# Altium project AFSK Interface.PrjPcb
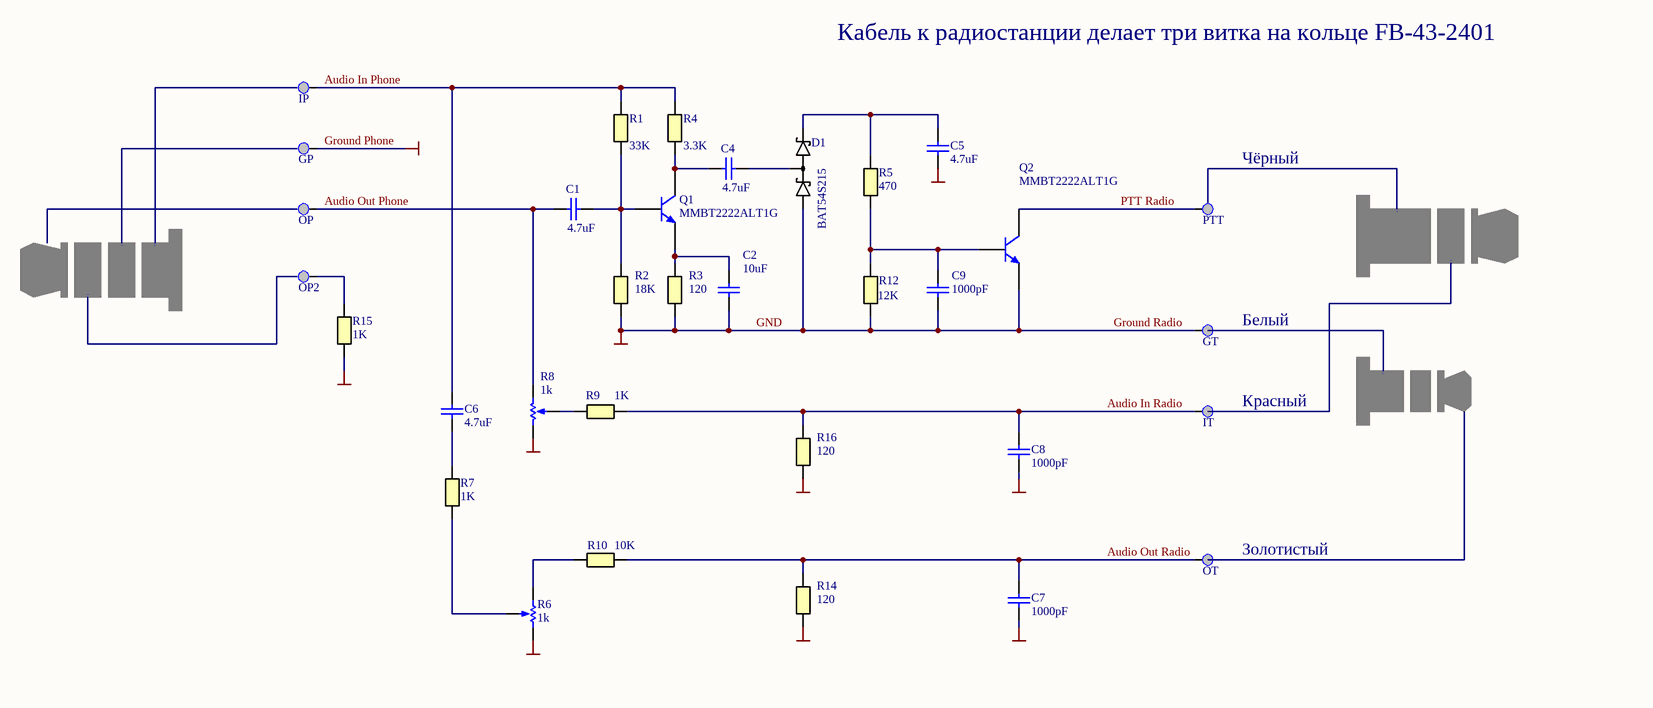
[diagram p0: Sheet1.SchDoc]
1 sheet, 33 parts. Net scope: global (net labels, ports and power ports of the same name join across sheets).
Board file: INTERFACE.PcbDoc

## Sheet Sheet1.SchDoc
size A3

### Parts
C1  value 4.7uF  [C0805]  (hidden comment: X7R-4.7UF-16V-20%-0805)
C2  value 10uF  [C0805]  (hidden comment: X5R-10UF-16V-20%-0805)
C4  value 4.7uF  [C0805]  (hidden comment: X7R-4.7UF-16V-20%-0805)
C5  value 4.7uF  [C0805]  (hidden comment: X7R-4.7UF-16V-20%-0805)
C6  value 4.7uF  [C0805]  (hidden comment: X7R-4.7UF-16V-20%-0805)
C7  value 1000pF  [C0805]  (hidden comment: NP0-1000PF-50V-5%-0805)
C8  value 1000pF  [C0805]  (hidden comment: NP0-1000PF-50V-5%-0805)
C9  value 1000pF  [C0805]  (hidden comment: NP0-1000PF-50V-5%-0805)
D1  BAT54S215  [SOT-23]
GP  PIN  [PIN]  (value not drawn)
GT  PIN  [PIN]  (value not drawn)
IP  PIN  [PIN]  (value not drawn)
IT  PIN  [PIN]  (value not drawn)
OP  PIN  [PIN]  (value not drawn)
OP2  PIN  [PIN]  (value not drawn)
OT  PIN  [PIN]  (value not drawn)
PTT  PIN  [PIN]  (value not drawn)
Q1  MMBT2222ALT1G  [SOT-23]
Q2  MMBT2222ALT1G  [SOT-23]
R1  value 33K  [R0805]  (hidden comment: 33K-0.125W-5%-0805)
R2  value 18K  [R0805]  (hidden comment: 18K-0.125W-5%-0805)
R3  value 120  [R0805]  (hidden comment: 120R-0.125W-5%-0805)
R4  value 3.3K  [R0805]  (hidden comment: 3.3K-0.125W-5%-0805)
R5  value 470  [R0805]  (hidden comment: 470R-0.125W-5%-0805)
R6  1k  [3306F]
R7  value 1K  [R0805]  (hidden comment: 1K-0.125W-5%-0805)
R8  1k  [3306F]
R9  value 1K  [R0805]  (hidden comment: 1K-0.125W-5%-0805)
R10  value 10K  [R0805]  (hidden comment: 10K-0.125W-5%-0805)
R12  value 12K  [R0805]  (hidden comment: 12K-0.125W-5%-0805)
R14  value 120  [R0805]  (hidden comment: 120R-0.125W-5%-0805)
R15  value 1K  [R0805]  (hidden comment: 1K-0.125W-5%-0805)
R16  value 120  [R0805]  (hidden comment: 120R-0.125W-5%-0805)

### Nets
GND: C2.1 C5.1 C7.2 C8.1 C9.1 D1.1 GP.1 GT.1 Q2.2(E) R2.1 R3.1 R6.3 R8.3 R12.1 R14.1 R15.1 R16.1  [also labelled Ground Phone, Ground Radio]
Audio In Phone: C6.1 IP.1 R1.2 R4.2
Audio In Radio: C8.2 IT.1 R9.2 R16.2
Audio Out Phone: C1.1 OP.1 R8.1
Audio Out Radio: C7.1 OT.1 R10.2 R14.2
PTT Radio: PTT.1 Q2.3(C)
NetC1_2: C1.2 Q1.1(B) R1.1 R2.2
NetC2_2: C2.2 Q1.2(E) R3.2
NetC4_1: C4.1 Q1.3(C) R4.1
NetC4_2: C4.2 D1.3
NetC5_2: C5.2 D1.2 R5.1
NetC6_2: C6.2 R7.1
NetC9_2: C9.2 Q2.1(B) R5.2 R12.2
NetOP2_1: OP2.1 R15.2
NetR6_1: R6.1 R10.1
NetR6_2: R6.2 R7.2
NetR8_2: R8.2 R9.1

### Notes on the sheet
- Кабель к радиостанции делает три витка на кольце FB-43-2401
- (near PTT) Чёрный
- (near GT) Белый
- (near IT) Красный
- (near OT) Золотистый

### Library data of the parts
C1 C4-C6 = CAP X7R-4.7UF-16V-20%-0805: CAP CER 4.7uF 16V 20% 0805; Class: Capacitor
C2 = CAP X5R-10UF-16V-20%-0805: CAP CER 10uF 16V 20% 0805; Class: Capacitor
C7-C9 = CAP NP0-1000PF-50V-5%-0805: CAP CER 1000pF 50V 5% NP0 0805; Class: Capacitor
D1 = BAT54S.215: DIODE ARRAY GP 30V 200MA SOT23-3; Manufacturer: NXP Semiconductor
GP GT IP IT OP OP2 OT PTT = PIN: 1 pin; ASSY_OPT: No Pop
Q1 Q2 = MMBT2222ALT1G: NPN General-purpose Transistor; Manufacturer: ON Semiconductor
R1 = RES 33K-0.125W-5%-0805: RESISTOR 0805 1/8W 33K Ohm 5%
R2 = RES 18K-0.125W-5%-0805: RESISTOR 0805 1/8W 18K Ohm 5%
R3 R14 R16 = RES 120R-0.125W-5%-0805: RESISTOR 0805 1/8W 120 Ohm 5%
R4 = RES 3.3K-0.125W-5%-0805: RESISTOR 0805 1/8W 3.3K Ohm 5%
R5 = RES 470R-0.125W-5%-0805: RESISTOR 0805 1/8W 470 Ohm 5%
R6 R8 = 3306F-1-102: Potentiometer; Manufacturer: Bourns Inc.; Class: Resistor
R7 R9 R15 = RES 1.0K-0.125W-5%-0805: RESISTOR 0805 1/8W 1K Ohm 5%
R10 = RES 10K-0.125W-5%-0805: RESISTOR 0805 1/8W 10K Ohm 5%
R12 = RES 12K-0.125W-5%-0805: RESISTOR 0805 1/8W 12K Ohm 5%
